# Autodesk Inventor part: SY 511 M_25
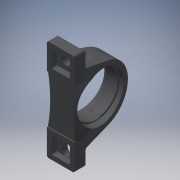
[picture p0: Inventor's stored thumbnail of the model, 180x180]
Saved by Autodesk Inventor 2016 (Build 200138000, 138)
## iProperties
Category: PARTsolutions
Company: SKF
Created: 2016-10
Part Number: SY 511 M_25
Catalog Web Link: www.cadenas.de
Description: housying__SY-Bearing units housings
Vendor: SKF
Document SubType Name: Modeling
Designer: psAdmin
Manufacturer: SKF
Mass: 406.909 g
Surface Area: 720.548 cm^2
Volume: 406.909 cm^3
Density: 1 g/cm^3
Material: Generic
Appearance: PSOLRGB-175-175-175
PSOL_IDENT_0: {$CADENAS_DATA\23d-libs\skf\skf_ps\bearing_units\housings\housing_sy.prj},172 {VTYP=3D},{NB=SY 511 M
PSOL_IDENT_1: _25},{LINA=SY 511 M_25},{NN=housying__SY},{DATE=12.09.2016 08:57:21},{GEOMDATE=17.05.2013 14:40:00},
PSOL_IDENT_2: {VERSION=},{LINEID=100},{LINESUBID=-1},{WBVAR=I}  {NB=SY 511 M_25},{LINA=SY 511 M_25},{KT=DUMMY},{PR
PSOL_IDENT_3: ODUCTID=211100511},{DESIGNATION=SY 511 M},{D=-1000000015047466219876688855040.000},{E=-1000000015047
PSOL_IDENT_4: 466219876688855040.000},{F=100.000},{G=60.000},{HX=40.000},{I=25},{IALG=25},{J=25},{K=-1000000015047
PSOL_IDENT_5: 466219876688855040.000},{LX=34},{M=-1000000015047466219876688855040.000},{N=126.000},{O=63.500},{P=2
PSOL_IDENT_6: 4.000},{Q=-1000000015047466219876688855040.000},{R=219.000},{SX=-1000000015047466219876688855040.000
PSOL_IDENT_7: },{T=162.000},{U=181.000},{V=171.500},{W=-1000000015047466219876688855040.000},{X=-10000000150474662
PSOL_IDENT_8: 19876688855040.000},{Y=27.500},{Z=18.000},{AA=5/8 in},{AB=-1000000015047466219876688855040.000},{AC=
PSOL_IDENT_9: -1000000015047466219876688855040.000},{AD=-1000000015047466219876688855040.000},{AE=16 mm},{AF=-1000
PSOL_IDENT_10: 000015047466219876688855040.000},{AG=-1000000015047466219876688855040.000},{AH=-10000000150474662198
PSOL_IDENT_11: 76688855040.000},{AI=-1000000015047466219876688855040.000},{AJ=-1000000015047466219876688855040.000}
PSOL_IDENT_12: ,{AK=-1000000015047466219876688855040.000},{AL=-1000000015047466219876688855040.000},{AM=-1000000015
PSOL_IDENT_13: 047466219876688855040.000},{AN=-1000000015047466219876688855040.000},{AO=-10000000150474662198766888
PSOL_IDENT_14: 55040.000},{AP=-1000000015047466219876688855040.000},{AQ=-1000000015047466219876688855040.000},{AR=-
PSOL_IDENT_15: 1000000015047466219876688855040.000},{AS=-1000000015047466219876688855040.000},{AT=-1000000015047466
PSOL_IDENT_16: 219876688855040.000},{AU=-1000000015047466219876688855040.000},{AV=-1000000015047466219876688855040.
PSOL_IDENT_17: 000},{AW=-1000000015047466219876688855040.000},{AX=-1000000015047466219876688855040.000},{AY=-100000
PSOL_IDENT_18: 0015047466219876688855040.000},{AZ=-1000000015047466219876688855040.000},{BA=-1000000015047466219876
PSOL_IDENT_19: 688855040.000},{BB=-1000000015047466219876688855040.000},{BC=-1000000015047466219876688855040.000},{
PSOL_IDENT_20: BD=-1000000015047466219876688855040.000},{BEX=-1000000015047466219876688855040.000},{BF=2.700},{BG=-
PSOL_IDENT_21: 1000000015047466219876688855040.000},{BH=-1000000015047466219876688855040.000},{BI=-1000000015047466
PSOL_IDENT_22: 219876688855040.000},{BJ=-1000000015047466219876688855040.000},{BK=-1000000015047466219876688855040.
PSOL_IDENT_23: 000},{BL=-1000000015047466219876688855040.000},{BM=-1000000015047466219876688855040.000},{BN=-100000
PSOL_IDENT_24: 0015047466219876688855040.000},{BO=-1000000015047466219876688855040.000},{BP=-1000000015047466219876
PSOL_IDENT_25: 688855040.000},{BQ=-1000000015047466219876688855040.000},{BR=-1000000015047466219876688855040.000},{
PSOL_IDENT_26: BS=-1000000015047466219876688855040.000},{BT=-1000000015047466219876688855040.000},{BU=-100000001504
PSOL_IDENT_27: 7466219876688855040.000},{BV=-1000000015047466219876688855040.000},{BW=-1000000015047466219876688855
PSOL_IDENT_28: 040.000},{BX=-1000000015047466219876688855040.000},{BY=-1000000015047466219876688855040.000},{BZ=-10
PSOL_IDENT_29: 00000015047466219876688855040.000},{CA=-1000000015047466219876688855040.000},{CB=-100000001504746621
PSOL_IDENT_30: 9876688855040.000},{CC=-1000000015047466219876688855040.000},{CD=-1000000015047466219876688855040.00
PSOL_IDENT_31: 0},{CE=-1000000015047466219876688855040.000},{CF=-1000000015047466219876688855040.000},{CG=-10000000
PSOL_IDENT_32: 15047466219876688855040.000},{CH=-1000000015047466219876688855040.000},{CI=-100000001504746621987668
PSOL_IDENT_33: 8855040.000},{CJ=-1000000015047466219876688855040.000},{CK=-1000000015047466219876688855040.000},{CL=
PSOL_IDENT_34: -1000000015047466219876688855040.000},{CM=-1000000015047466219876688855040.000},{CN=-100000001504746
PSOL_IDENT_35: 6219876688855040.000},{CO=-1000000015047466219876688855040.000},{CP=-1000000015047466219876688855040
PSOL_IDENT_36: .000},{CQ=-1000000015047466219876688855040.000},{CR=-1000000015047466219876688855040.000},{CS=-10000
PSOL_IDENT_37: 00015047466219876688855040.000},{CT=-1000000015047466219876688855040.000},{CU=-100000001504746621987
PSOL_IDENT_38: 6688855040.000},{CV=-1000000015047466219876688855040.000},{CW=-1000000015047466219876688855040.000},
PSOL_IDENT_39: {CX=-1000000015047466219876688855040.000},{CY=-1000000015047466219876688855040.000},{CZ=-10000000150
PSOL_IDENT_40: 47466219876688855040.000},{DA=-1000000015047466219876688855040.000},{DB=-100000001504746621987668885
PSOL_IDENT_41: 5040.000},{DC=-1000000015047466219876688855040.000},{DD=-1000000015047466219876688855040.000},{DEX=-
PSOL_IDENT_42: 1000000015047466219876688855040.000},{DF=-1000000015047466219876688855040.000},{DG=-1000000015047466
PSOL_IDENT_43: 219876688855040.000},{DH=-1000000015047466219876688855040.000},{TYPEID=211100},{INFO=LINK},{A=60},{A
PSOL_IDENT_44: 1=40},{DE=100},{H=126},{H1=63.5},{H2=24},{N1=18},{L=219},{JMIN=162},{JMAX=181},{SY0=0},{SX0=0},{KX0=
PSOL_IDENT_45: 0},{ANGLE=15},{FX0=0},{SH=11.7},{R0X=62.5},{R1=52.5},{SKFPLAN=2.5},{TXTANG=14.638526},{SB1=14.625},{
PSOL_IDENT_46: AAA=22},{BE=25}
NN: housying__SY
NT: Bearing units housings
NB: SY 511 M_25
NBSYN: $DESIGNATION._$I.
LINA: SY 511 M_25
PRODUCTID: 211100511
DESIGNATION: SY 511 M
F: 100.000
G: 60.000
HX: 40.000
I: 25
J: 25
LX: 34
N: 126.000
O: 63.500
P: 24.000
R: 219.000
T: 162.000
U: 181.000
V: 171.500
Y: 27.500
Z: 18.000
AA: 5/8 in
AE: 16 mm
BF: 2.700
TYPEID: 211100
INFO: LINK
SUPPLIER: SKF
ARTICLENO: SY 511 M_25
BOMINFO: SY 511 M_25
CREATOR: CADENAS GmbH
Title: SY 511 M_25
Author: Cadenas PARTsolutions
Comments: Bearing units housings
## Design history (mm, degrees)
sketch "Sketch_1"
  geometry: L1 (-30, -44.343)-(-30, -63.5); L2 (-30, -63.5)-(30, -63.5); L3 (30, -63.5)-(30, -44.343); L4 (29.532, -34.68)-(20, 63.5); L5 (20, 63.5)-(-20, 63.5); L6 (-20, 63.5)-(-29.532, -34.68); A1 r 100 centre (-70, -44.343) between (30, -44.343) and (29.532, -34.68); A2 r 100 centre (70, -44.343) between (-29.532, -34.68) and (-30, -44.343)
  constraints: 12 end point, 4 point on circle, 2 centre point
extrude "Extrusion1" join sketch "Sketch_1" stored distance "d0" = 438; taper "d1" = 0 deg
sketch "Sketch_2"
  geometry: L1 (-219, -63.5)-(-109.5, -63.5); L2 (-109.5, -63.5)-(-109.5, -44.3); L3 (-104.7, -39.5)-(-79.125, -39.5); L4 (-74.296, -35.794)-(-60.37, 16.176); L5 (60.37, 16.176)-(74.296, -35.794); L6 (79.125, -39.5)-(104.7, -39.5); L7 (109.5, -44.3)-(109.5, -63.5); L8 (109.5, -63.5)-(219, -63.5); L9 (219, -63.5)-(219, 86.5); L10 (219, 86.5)-(-219, 86.5); L11 (-219, 86.5)-(-219, -63.5); A1 r 4.8 centre (-104.7, -44.3) between (-104.7, -39.5) and (-109.5, -44.3); A2 r 5 centre (-79.125, -34.5) between (-79.125, -39.5) and (-74.296, -35.794); A3 r 62.5 centre (0, 0) between (60.37, 16.176) and (-60.37, 16.176); A4 r 5 centre (79.125, -34.5) between (74.296, -35.794) and (79.125, -39.5); A5 r 4.8 centre (104.7, -44.3) between (109.5, -44.3) and (104.7, -39.5)
  constraints: 22 end point, 10 point on circle, 5 centre point
extrude "Extrusion2" cut sketch "Sketch_2" stored distance "d2" = 438; taper "d3" = 0 deg
sketch "Sketch_3"
  geometry: C1 r 52.5 at (0, 0); 1 further point
  constraints: 1 centre point
extrude "Extrusion3" cut sketch "Sketch_3" stored distance "d4" = 438; taper "d5" = 0 deg
sketch "Sketch_4"
  geometry: L1 (12.5, 0)-(-12.5, 0); L2 (12.5, 48.412)-(12.5, 52.5); L3 (12.5, 52.5)-(-12.5, 52.5); L4 (-12.5, 52.5)-(-12.5, 48.412); A1 r 50 centre (0, 0) between (12.5, 48.412) and (-12.5, 48.412)
  constraints: 8 end point, 2 point on circle, 1 centre point
revolve "Revolution1" sketch "Sketch_4" stored, may be unused: angle "d6" = 360 deg
sketch "Sketch_5"
  geometry: L1 (-9, -81)-(-9, -90.5); L2 (9, -90.5)-(9, -81); A1 r 9 centre (0, -90.5) between (-9, -90.5) and (9, -90.5); A2 r 9 centre (0, -81) between (9, -81) and (-9, -81)
  constraints: 4 end point, 4 point on circle, 2 centre point
extrude "Extrusion4" cut sketch "Sketch_5" stored distance "d7" = 96; taper "d8" = 0 deg
sketch "Sketch_6"
  geometry: L1 (9, 81)-(9, 90.5); L2 (-9, 90.5)-(-9, 81); A1 r 9 centre (0, 81) between (-9, 81) and (9, 81); A2 r 9 centre (0, 90.5) between (9, 90.5) and (-9, 90.5)
  constraints: 4 end point, 4 point on circle, 2 centre point
extrude "Extrusion5" cut sketch "Sketch_6" stored distance "d9" = 96; taper "d10" = 0 deg
sketch "Sketch_7"
  geometry: C1 r 18 at (0, -81); 1 further point
  constraints: 1 centre point
extrude "Extrusion6" cut sketch "Sketch_7" distance "d11" = 102; taper "d12" = 0 deg
sketch "Sketch_8"
  geometry: C1 r 18 at (0, 81); 1 further point
  constraints: 1 centre point
extrude "Extrusion7" cut sketch "Sketch_8" distance "d13" = 102; taper "d14" = 0 deg
sketch "Sketch_9"
  geometry: L1 (-65, -52.5)-(-30, -52.5); L2 (-30, 52.5)-(-65, 52.5); L3 (-65, 52.5)-(-65, -52.5); A1 r 278.125 centre (-303.125, 0) between (-30, -52.5) and (-30, 52.5)
  constraints: 6 end point, 2 point on circle, 1 centre point
extrude "Extrusion8" cut sketch "Sketch_9" distance "d15" = 127; taper "d16" = 0 deg
sketch "Sketch_10"
  geometry: L1 (30, -52.5)-(65, -52.5); L2 (65, -52.5)-(65, 52.5); L3 (65, 52.5)-(30, 52.5); A1 r 278.125 centre (303.125, 0) between (30, 52.5) and (30, -52.5)
  constraints: 6 end point, 2 point on circle, 1 centre point
extrude "Extrusion9" cut sketch "Sketch_10" stored distance "d17" = 254; taper "d18" = 0 deg
sketch "Sketch_11"
  geometry: L1 (-22.883, 58.672)-(-21.82, 55.946); L2 (-8.327, 59.47)-(-8.733, 62.368); L3 (-8.733, 62.368)-(-22.883, 58.672); A1 r 60.05 centre (0, 0) between (-8.327, 59.47) and (-21.82, 55.946)
  constraints: 6 end point, 2 point on circle, 1 centre point
extrude "Extrusion10" join sketch "Sketch_11" distance "d19" = 11.7; taper "d20" = 0 deg
sketch "Skizze_1"
  geometry: L1 (0, 3.9)-(0, 0.488); L2 (0.488, 0)-(14.138, 0); L3 (14.625, 0.488)-(14.625, 6.825); L4 (14.138, 7.313)-(6.338, 7.313); L5 (5.85, 7.8)-(5.85, 9.75); L6 (6.338, 10.238)-(8.288, 10.238); L7 (8.775, 9.75)-(8.775, 9.262); L8 (9.263, 8.775)-(12.675, 8.775); L9 (13.163, 9.262)-(13.163, 11.213); L10 (12.675, 11.7)-(1.95, 11.7); L11 (1.463, 11.213)-(1.463, 6.338); L12 (1.95, 5.85)-(9.75, 5.85); L13 (10.238, 5.362)-(10.238, 1.95); L14 (9.75, 1.462)-(4.875, 1.462); L15 (4.388, 1.95)-(4.388, 3.9); L16 (3.9, 4.388)-(0.488, 4.388); A1 r 0.488 centre (0.488, 0.488) between (0, 0.488) and (0.488, 0); A2 r 0.488 centre (14.137, 0.488) between (14.138, 0) and (14.625, 0.488); A3 r 0.488 centre (14.137, 6.825) between (14.625, 6.825) and (14.138, 7.313); A4 r 0.488 centre (6.338, 7.8) between (5.85, 7.8) and (6.338, 7.313); A5 r 0.488 centre (6.338, 9.75) between (6.338, 10.238) and (5.85, 9.75); A6 r 0.488 centre (8.287, 9.75) between (8.775, 9.75) and (8.288, 10.238); A7 r 0.488 centre (9.263, 9.263) between (8.775, 9.262) and (9.263, 8.775); A8 r 0.488 centre (12.675, 9.263) between (12.675, 8.775) and (13.163, 9.262); A9 r 0.488 centre (12.675, 11.212) between (13.163, 11.213) and (12.675, 11.7); A10 r 0.488 centre (1.95, 11.212) between (1.95, 11.7) and (1.463, 11.213); A11 r 0.488 centre (1.95, 6.338) between (1.463, 6.338) and (1.95, 5.85); A12 r 0.488 centre (9.75, 5.362) between (10.238, 5.362) and (9.75, 5.85); A13 r 0.488 centre (9.75, 1.95) between (9.75, 1.462) and (10.238, 1.95); A14 r 0.488 centre (4.875, 1.95) between (4.388, 1.95) and (4.875, 1.462); A15 r 0.488 centre (3.9, 3.9) between (4.388, 3.9) and (3.9, 4.388); A16 r 0.488 centre (0.488, 3.9) between (0.488, 4.388) and (0, 3.9)
  constraints: 32 end point, 32 point on circle, 16 centre point
extrude "Extrusion11" join sketch "Skizze_1" stored distance "d21" = 1.6; taper "d22" = 0 deg
sketch "Sketch_12"
  geometry: L1 (-7.556, 63.05)-(-7.556, 60.55); L2 (-7.556, 60.55)-(7.556, 60.55); L3 (7.556, 60.55)-(7.556, 63.05); L4 (7.556, 63.05)-(-7.556, 63.05)
  constraints: 8 end point
extrude "Extrusion12" join sketch "Sketch_12" distance "d23" = 11.7; taper "d24" = 0 deg
sketch "Sketch_13"
  geometry: L1 (0, -0.487)-(0, -4.388); L2 (0.488, -4.875)-(4.388, -4.875); L3 (4.388, -4.875)-(0.143, -9.12); L4 (0, -9.464)-(0, -14.625); L5 (0.488, -15.113)-(3.9, -15.113); L6 (4.388, -14.625)-(4.388, -11.393); L7 (4.505, -11.076)-(7.313, -7.8); L8 (7.313, -7.8)-(8.632, -9.12); L9 (8.775, -9.464)-(8.775, -13.163); L10 (9.262, -13.65)-(11.213, -13.65); L11 (11.7, -13.163)-(11.7, -8.994); L12 (11.536, -8.63)-(7.313, -4.875); L13 (7.313, -4.875)-(11.213, -4.875); L14 (11.7, -4.388)-(11.7, -0.487); L15 (11.213, 0)-(8.002, 0); L16 (7.657, -0.143)-(7.455, -0.345); L17 (7.111, -0.487)-(5.077, -0.487); L18 (4.732, -0.345)-(4.53, -0.143); L19 (4.186, 0)-(0.488, 0); A1 r 0.488 centre (0.488, -4.387) between (0, -4.388) and (0.488, -4.875); A2 r 0.488 centre (0.488, -9.464) between (0.143, -9.12) and (0, -9.464); A3 r 0.488 centre (0.488, -14.625) between (0, -14.625) and (0.488, -15.113); A4 r 0.488 centre (3.9, -14.625) between (3.9, -15.113) and (4.388, -14.625); A5 r 0.488 centre (4.875, -11.393) between (4.505, -11.076) and (4.388, -11.393); A6 r 0.487 centre (8.288, -9.464) between (8.775, -9.464) and (8.632, -9.12); A7 r 0.488 centre (9.263, -13.162) between (8.775, -13.163) and (9.262, -13.65); A8 r 0.488 centre (11.212, -13.162) between (11.213, -13.65) and (11.7, -13.163); A9 r 0.488 centre (11.212, -8.994) between (11.7, -8.994) and (11.536, -8.63); A10 r 0.488 centre (11.212, -4.387) between (11.213, -4.875) and (11.7, -4.388); A11 r 0.488 centre (11.212, -0.488) between (11.7, -0.487) and (11.213, 0); A12 r 0.488 centre (8.002, -0.488) between (8.002, 0) and (7.657, -0.143); A13 r 0.488 centre (7.111, 0) between (7.111, -0.487) and (7.455, -0.345); A14 r 0.488 centre (5.077, 0) between (4.732, -0.345) and (5.077, -0.487); A15 r 0.488 centre (4.186, -0.488) between (4.53, -0.143) and (4.186, 0); A16 r 0.488 centre (0.488, -0.488) between (0.488, 0) and (0, -0.487)
  constraints: 38 end point, 32 point on circle, 16 centre point
extrude "Extrusion13" join sketch "Sketch_13" stored distance "d25" = 1.6; taper "d26" = 0 deg
sketch "Sketch_14"
  geometry: L1 (7.747, 60.041)-(22.605, 56.16); L2 (22.605, 56.16)-(23.237, 58.579); L3 (23.237, 58.579)-(8.379, 62.46); L4 (8.379, 62.46)-(7.747, 60.041)
  constraints: 8 end point
extrude "Extrusion14" join sketch "Sketch_14" distance "d27" = 11.7; taper "d28" = 0 deg
sketch "Sketch_15"
  geometry: L1 (0.487, 0)-(4.388, 0); L2 (4.875, 0.488)-(4.875, 3.9); L3 (3.9, 4.875)-(3.9, 5.362); L4 (4.388, 5.85)-(6.136, 5.85); L5 (6.48, 5.707)-(6.682, 5.505); L6 (7.027, 5.362)-(10.238, 5.362); L7 (10.725, 5.85)-(10.725, 7.313); L8 (10.238, 7.8)-(7.027, 7.8); L9 (6.682, 7.657)-(6.48, 7.455); L10 (6.136, 7.313)-(4.388, 7.313); L11 (3.9, 7.8)-(3.9, 9.75); L12 (4.388, 10.238)-(8.775, 10.238); L13 (9.263, 9.75)-(9.263, 9.262); L14 (9.75, 8.775)-(14.576, 8.775); L15 (15.064, 9.262)-(15.064, 11.213); L16 (14.576, 11.7)-(0.487, 11.7); L17 (0, 11.213)-(0, 8.002); L18 (0.143, 7.657)-(0.345, 7.455); L19 (0.487, 7.111)-(0.487, 4.589); L20 (0.345, 4.245)-(0.143, 4.043); L21 (0, 3.698)-(0, 0.488); A1 r 0.488 centre (0.488, 0.488) between (0, 0.488) and (0.487, 0); A2 r 0.488 centre (4.387, 0.488) between (4.388, 0) and (4.875, 0.488); A3 r 0.488 centre (4.387, 3.9) between (4.875, 3.9) and (4.387, 4.388); A4 r 0.488 centre (4.388, 4.875) between (3.9, 4.875) and (4.387, 4.388); A5 r 0.488 centre (4.388, 5.362) between (4.388, 5.85) and (3.9, 5.362); A6 r 0.487 centre (6.136, 5.363) between (6.48, 5.707) and (6.136, 5.85); A7 r 0.487 centre (7.027, 5.85) between (6.682, 5.505) and (7.027, 5.362); A8 r 0.488 centre (10.237, 5.85) between (10.238, 5.362) and (10.725, 5.85); A9 r 0.488 centre (10.237, 7.312) between (10.725, 7.313) and (10.238, 7.8); A10 r 0.487 centre (7.027, 7.313) between (7.027, 7.8) and (6.682, 7.657); A11 r 0.487 centre (6.136, 7.8) between (6.136, 7.313) and (6.48, 7.455); A12 r 0.488 centre (4.388, 7.8) between (3.9, 7.8) and (4.388, 7.313); A13 r 0.488 centre (4.388, 9.75) between (4.388, 10.238) and (3.9, 9.75); A14 r 0.488 centre (8.775, 9.75) between (9.263, 9.75) and (8.775, 10.238); A15 r 0.488 centre (9.75, 9.263) between (9.263, 9.262) and (9.75, 8.775); A16 r 0.488 centre (14.576, 9.263) between (14.576, 8.775) and (15.064, 9.262); A17 r 0.488 centre (14.576, 11.212) between (15.064, 11.213) and (14.576, 11.7); A18 r 0.488 centre (0.488, 11.212) between (0.487, 11.7) and (0, 11.213); A19 r 0.488 centre (0.488, 8.002) between (0, 8.002) and (0.143, 7.657); A20 r 0.488 centre (0, 7.111) between (0.487, 7.111) and (0.345, 7.455); A21 r 0.488 centre (0, 4.589) between (0.345, 4.245) and (0.487, 4.589); A22 r 0.488 centre (0.488, 3.698) between (0.143, 4.043) and (0, 3.698)
  constraints: 44 point on circle, 42 end point, 22 centre point
extrude "Extrusion15" join sketch "Sketch_15" distance "d29" = 1; taper "d30" = 0 deg
sketch "Sketch_16"
  geometry: L1 (-12.5, 0)-(12.5, 0); L2 (12.5, 0)-(12.5, -50); L3 (12.5, -50)-(-12.5, -50); L4 (-12.5, -50)-(-12.5, 0); L5 (-12.5, 0)-(12.5, 0)
  constraints: 10 end point
revolve "Revolution2" sketch "Sketch_16" stored, may be unused: angle "d31" = 28.0725 deg
sketch "Sketch_17"
  geometry: L1 (12.5, 0)-(-12.5, 0); L2 (-12.5, 0)-(-12.5, 50); L3 (-12.5, 50)-(12.5, 50); L4 (12.5, 50)-(12.5, 0); L5 (12.5, 0)-(-12.5, 0)
  constraints: 10 end point
revolve "Revolution3" sketch "Sketch_17" stored, may be unused: angle "d32" = 28.0725 deg
sketch "Sketch_18"
  geometry: L1 (-52.5, -61.3)-(-52.5, -63.5); L2 (-52.5, -63.5)-(52.5, -63.5); L3 (52.5, -63.5)-(52.5, -61.3); L4 (52.5, -61.3)-(-52.5, -61.3)
  constraints: 8 end point
extrude "Extrusion16" cut sketch "Sketch_18" stored distance "d33" = 120; taper "d34" = 0 deg
sketch "Sketch_19"
  geometry: L1 (-60, -114.5)-(60, -114.5); L2 (60, -114.5)-(60, 114.5); L3 (60, 114.5)-(-60, 114.5); L4 (-60, 114.5)-(-60, -114.5); L5 (-30, 105.5)-(-30, -105.5); L6 (-26, -109.5)-(26, -109.5); L7 (30, -105.5)-(30, 105.5); L8 (26, 109.5)-(-26, 109.5); A1 r 4 centre (-26, -105.5) between (-30, -105.5) and (-26, -109.5); A2 r 4 centre (26, -105.5) between (26, -109.5) and (30, -105.5); A3 r 4 centre (26, 105.5) between (30, 105.5) and (26, 109.5); A4 r 4 centre (-26, 105.5) between (-26, 109.5) and (-30, 105.5)
  constraints: 16 end point, 8 point on circle, 4 centre point
extrude "Extrusion17" cut sketch "Sketch_19" stored distance "d35" = 50; taper "d36" = 0 deg
sketch "Sketch_20"
  geometry: L1 (-20, -66.5)-(-20, -95.5); L2 (-16, -99.5)-(16, -99.5); L3 (20, -95.5)-(20, -66.5); L4 (16, -62.5)-(-16, -62.5); A1 r 4 centre (-16, -95.5) between (-20, -95.5) and (-16, -99.5); A2 r 4 centre (16, -95.5) between (16, -99.5) and (20, -95.5); A3 r 4 centre (16, -66.5) between (20, -66.5) and (16, -62.5); A4 r 4 centre (-16, -66.5) between (-16, -62.5) and (-20, -66.5)
  constraints: 8 end point, 8 point on circle, 4 centre point
extrude "Extrusion18" cut sketch "Sketch_20" distance "d37" = 12; taper "d38" = 0 deg
sketch "Sketch_21"
  geometry: L1 (-20, 95.5)-(-20, 66.5); L2 (-16, 62.5)-(16, 62.5); L3 (20, 66.5)-(20, 95.5); L4 (16, 99.5)-(-16, 99.5); A1 r 4 centre (-16, 66.5) between (-20, 66.5) and (-16, 62.5); A2 r 4 centre (16, 66.5) between (16, 62.5) and (20, 66.5); A3 r 4 centre (16, 95.5) between (20, 95.5) and (16, 99.5); A4 r 4 centre (-16, 95.5) between (-16, 99.5) and (-20, 95.5)
  constraints: 8 end point, 8 point on circle, 4 centre point
extrude "Extrusion19" cut sketch "Sketch_21" distance "d39" = 12; taper "d40" = 0 deg
node "sy_XY"
node "sy_YZ"
node "sy_ZX"
node "sy_X"
node "sy_Y"
node "sy_Z"
node "sy_Center"
node "to_end_cover_XY"
node "to_end_cover_YZ"
node "to_end_cover_ZX"
node "to_end_cover_X"
node "to_end_cover_Y"
node "to_end_cover_Z"
node "to_end_cover_Center"
body "Solid1"
other parameters: "d41" = 0, "d42" = 0
